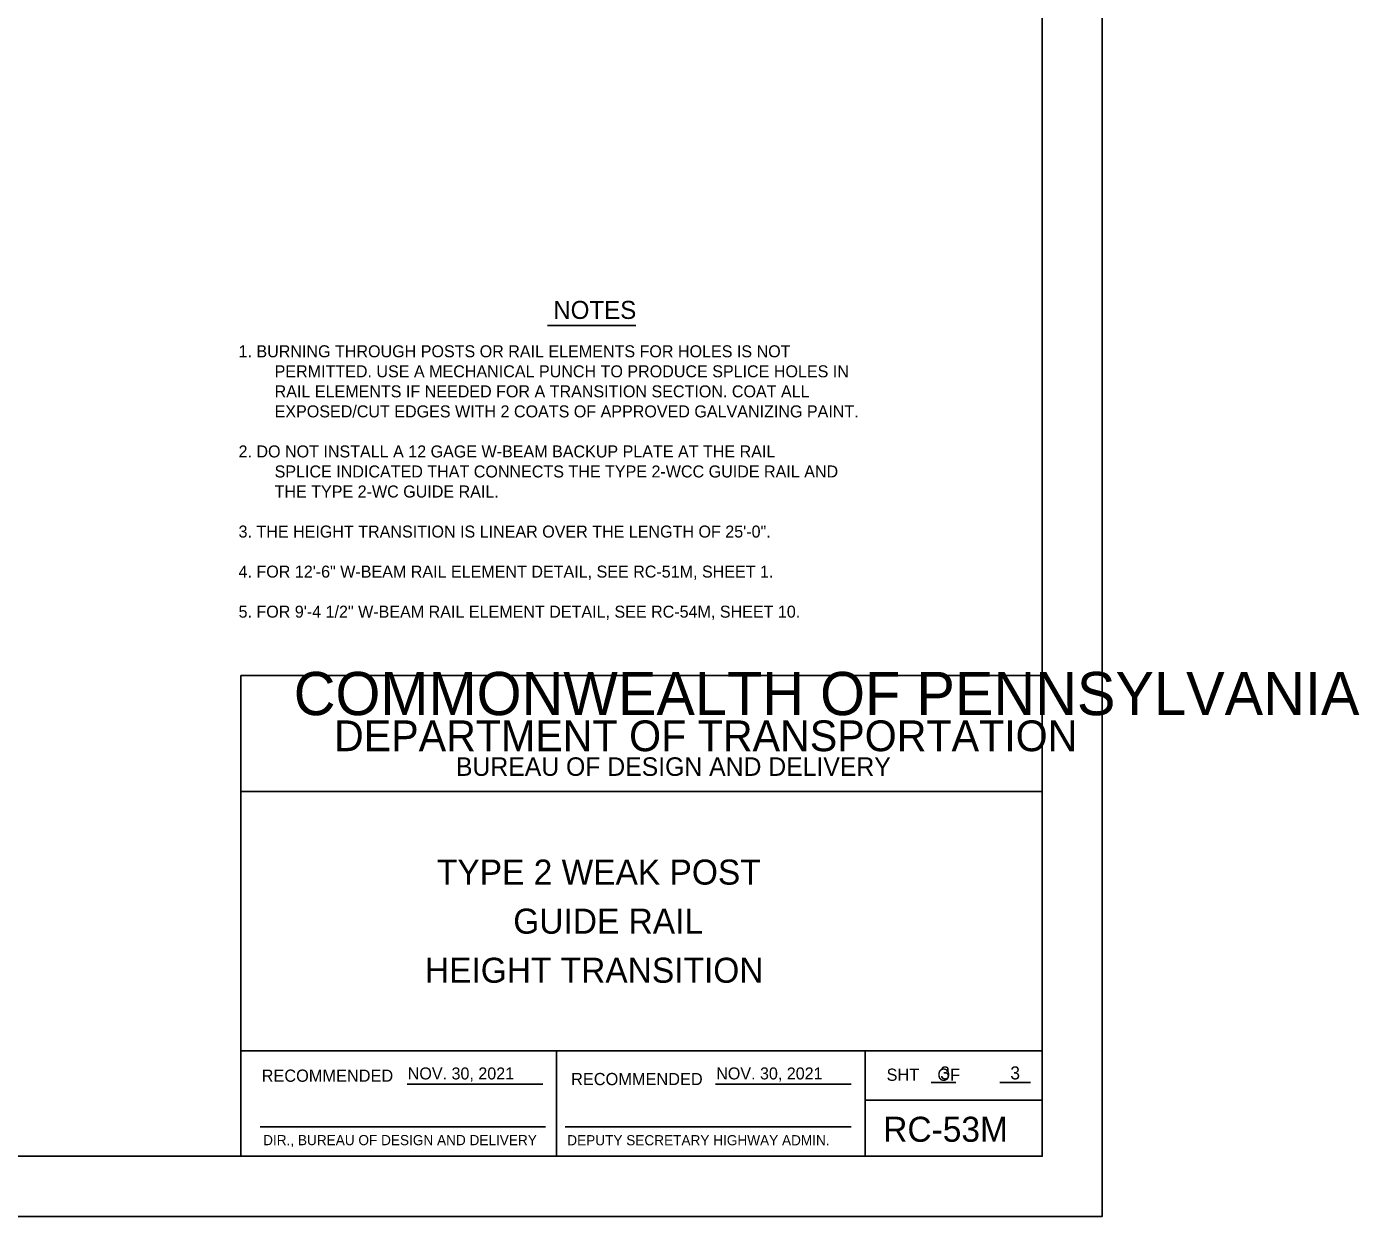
# Model space of a CAD drawing. Extents: x 637628 to 640188, y 298266 to 300751.
# Drawn here: x 639692 to 640024.7, y 298859.6 to 299156.6 of the extents above; entities that cross this region are included whole.
import ezdxf

# ---------------------------------------------------------------- set-up
doc = ezdxf.new("R2010")
doc.units = 0
for name, color, linetype in [('1', 7, 'Continuous'), ('3', 7, 'Continuous'), ('PLT-BNDY', 7, 'Continuous')]:
    doc.layers.add(name, color=color, linetype=linetype)

msp = doc.modelspace()

# ---------------------------------------------------------------- linework, layer by layer
at = {"layer": '1'}
for p, q in [((639787, 298892.56), (639820.88, 298892.56)), ((639863.99, 298892.56), (639897.86, 298892.56)), ((639917.83, 298892.95), (639923.97, 298892.95)), ((639934.95, 298892.95), (639942.6, 298892.95)), ((639750.29, 298881.9), (639821.54, 298881.9)), ((639826.46, 298881.9), (639897.8, 298881.9))]:
    msp.add_line(p, q, dxfattribs=at)
msp.add_lwpolyline([(639945.52, 298874.58), (639945.52, 299438.55), (639159.55, 299438.55), (639159.55, 298874.58), (639945.52, 298874.58), (639945.52, 298900.93), (639745.53, 298900.93), (639745.53, 298965.61), (639945.52, 298965.61), (639945.52, 298994.57), (639745.53, 298994.57), (639745.53, 298874.58), (639824.33, 298874.58), (639824.33, 298900.93), (639824.33, 298874.58), (639901.33, 298874.58), (639901.33, 298900.93), (639901.33, 298888.62), (639945.52, 298888.62)], dxfattribs=at)
at = {"layer": '3'}
msp.add_line((639822.08, 299081.96), (639844.12, 299081.96), dxfattribs=at)
at = {"layer": 'PLT-BNDY'}
msp.add_lwpolyline([(639119.52, 299453.58), (639960.52, 299453.58), (639960.52, 298859.58), (639119.52, 298859.58)], close=True, dxfattribs=at)

# ---------------------------------------------------------------- texts
at = {"layer": '1'}
for s, height, p in [('COMMONWEALTH OF PENNSYLVANIA', 10.7834, (639758.71, 298984.7)), ('DEPARTMENT OF TRANSPORTATION', 7.6843, (639768.77, 298975.7)), ('BUREAU OF DESIGN AND DELIVERY', 4.6221, (639799.2, 298969.54)), ('TYPE 2 WEAK POST', 6.25, (639794.45, 298942.39)), ('GUIDE RAIL', 6.25, (639813.5, 298930.14)), ('HEIGHT TRANSITION', 6.25, (639791.45, 298917.89)), ('RECOMMENDED', 3.048, (639750.7, 298893.17)), ('NOV. 30, 2021', 3, (639787.17, 298893.75)), ('RECOMMENDED', 3.048, (639827.94, 298892.33)), ('NOV. 30, 2021', 3, (639864.16, 298893.75)), ('SHT    OF', 3.048, (639906.68, 298893.41)), ('APPROVED', 0.0192, (639788.55, 298892.51)), ('RC-53M', 6.25, (639905.85, 298878.19)), ('DIR., BUREAU OF DESIGN AND DELIVERY', 2.54, (639751.07, 298877.34)), ('DEPUTY SECRETARY HIGHWAY ADMIN.', 2.54, (639826.98, 298877.31))]:
    msp.add_text(s, height=height, dxfattribs=at).set_placement(p)
at = {"layer": '3'}
for s, height, p in [('NOTES', 4.5, (639823.48, 299083.61)), ('1. BURNING THROUGH POSTS OR RAIL ELEMENTS FOR HOLES IS NOT ', 3, (639744.94, 299074.03)), ('PERMITTED. USE A MECHANICAL PUNCH TO PRODUCE SPLICE HOLES IN ', 3, (639753.94, 299069.03)), ('RAIL ELEMENTS IF NEEDED FOR A TRANSITION SECTION. COAT ALL ', 3, (639753.94, 299064.03)), ('EXPOSED/CUT EDGES WITH 2 COATS OF APPROVED GALVANIZING PAINT.', 3, (639753.94, 299059.03)), ('2. DO NOT INSTALL A 12 GAGE W-BEAM BACKUP PLATE AT THE RAIL ', 3, (639744.94, 299049.03)), ('SPLICE INDICATED THAT CONNECTS THE TYPE 2-WCC GUIDE RAIL AND ', 3, (639753.94, 299044.03)), ('THE TYPE 2-WC GUIDE RAIL. ', 3, (639753.94, 299039.03)), ('3. THE HEIGHT TRANSITION IS LINEAR OVER THE LENGTH OF 25\'-0".', 3, (639744.94, 299029.03)), ('4. FOR 12\'-6" W-BEAM RAIL ELEMENT DETAIL, SEE RC-51M, SHEET 1.', 3, (639744.94, 299019.03)), ('5. FOR 9\'-4 1/2" W-BEAM RAIL ELEMENT DETAIL, SEE RC-54M, SHEET 10.', 3, (639744.94, 299009.03)), ('3', 3.25, (639920.07, 298893.76)), ('3', 3.25, (639937.56, 298893.76))]:
    msp.add_text(s, height=height, dxfattribs=at).set_placement(p)

doc.saveas('drawing.dxf')
